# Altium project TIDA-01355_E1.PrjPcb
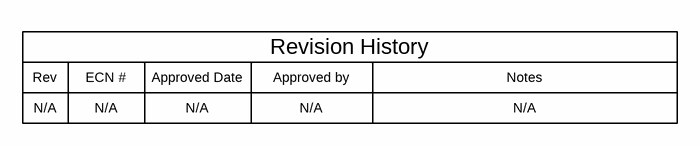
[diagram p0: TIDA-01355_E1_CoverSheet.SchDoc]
CopyrightYear: 2016; PCB_Layout: Sharad Yadav; PCB_Rev: E1; PRJ_Customer: Public Release; PRJ_Engineer: Sharad Yadav; PRJ_Number: XX####; PRJ_Title: 73dB SNR, 7.5MSPS, 14-bit Analog Front-end Using Time-Interleaved SAR ADCs; SCH_Rev: E1; TechSupport: http://www.ti.com/support; TID: TIDA-01355
3 sheets, 92 parts. Net scope: global (net labels, ports and power ports of the same name join across sheets).
Board file: TIDA-01355_E1_PCB.PcbDoc
Sheets:
  TIDA-01355_E1_CoverSheet.SchDoc
  TIDA-01355_E1_EVM_Hardware.SchDoc
  TIDA-01355_E1_AFE_Circuit.SchDoc

## Sheet TIDA-01355_E1_CoverSheet.SchDoc: Block Diagram
size 431 x 279 mm; Date: Not shown in title block; ApprovedBy: Not shown in title block; CheckedBy: Not shown in title block; Author: Not shown in title block; CompanyName: Not shown in title block; DrawnBy: Sharad Yadav; Engineer: Sharad Yadav; Organization: Not shown in title block; Address1: Not shown in title block; Address2: Not shown in title block; Address3: Not shown in title block; Address4: Not shown in title block; DocumentNumber: 1; Revision: Use project parameter SCH_Rev; SheetNumber: 1; SheetTotal: 3; PageSetup: Record=PageOptions¦CenterHorizontal=True¦CenterVertical=True¦PrintScale=1.00¦XCorrection=1.00¦YCorrection=1.00¦PrintKind=0¦BorderSize=5000000¦LeftOffset=0¦BottomOffset=0¦Orientation=2¦PaperLength=1000¦PaperWidth=1000¦Scale=100¦PaperSource=15¦PrintQuality=600¦MediaType=1¦DitherType=10¦PaperKind=Letter¦PrintScaleMode=1

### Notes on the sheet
- Rev
- N/A
- ECN #
- Approved Date
- Approved by
- Revision History
- Notes

## Sheet TIDA-01355_E1_EVM_Hardware.SchDoc: Hardware
size 431 x 279 mm; Date: Not shown in title block; ApprovedBy: Not shown in title block; CheckedBy: Not shown in title block; Author: Not shown in title block; CompanyName: Not shown in title block; DrawnBy: Sharad Yadav; Engineer: Sharad Yadav; Organization: Not shown in title block; Address1: Not shown in title block; Address2: Not shown in title block; Address3: Not shown in title block; Address4: Not shown in title block; DocumentNumber: 1; Revision: Use project parameter SCH_Rev; SheetNumber: 3; SheetTotal: 3; PageSetup: Record=PageOptions¦CenterHorizontal=True¦CenterVertical=True¦PrintScale=1.00¦XCorrection=1.00¦YCorrection=1.00¦PrintKind=0¦BorderSize=5000000¦LeftOffset=0¦BottomOffset=0¦Orientation=2¦PaperLength=1000¦PaperWidth=1000¦Scale=100¦PaperSource=15¦PrintQuality=600¦MediaType=1¦DitherType=10¦PaperKind=Letter¦PrintScaleMode=1
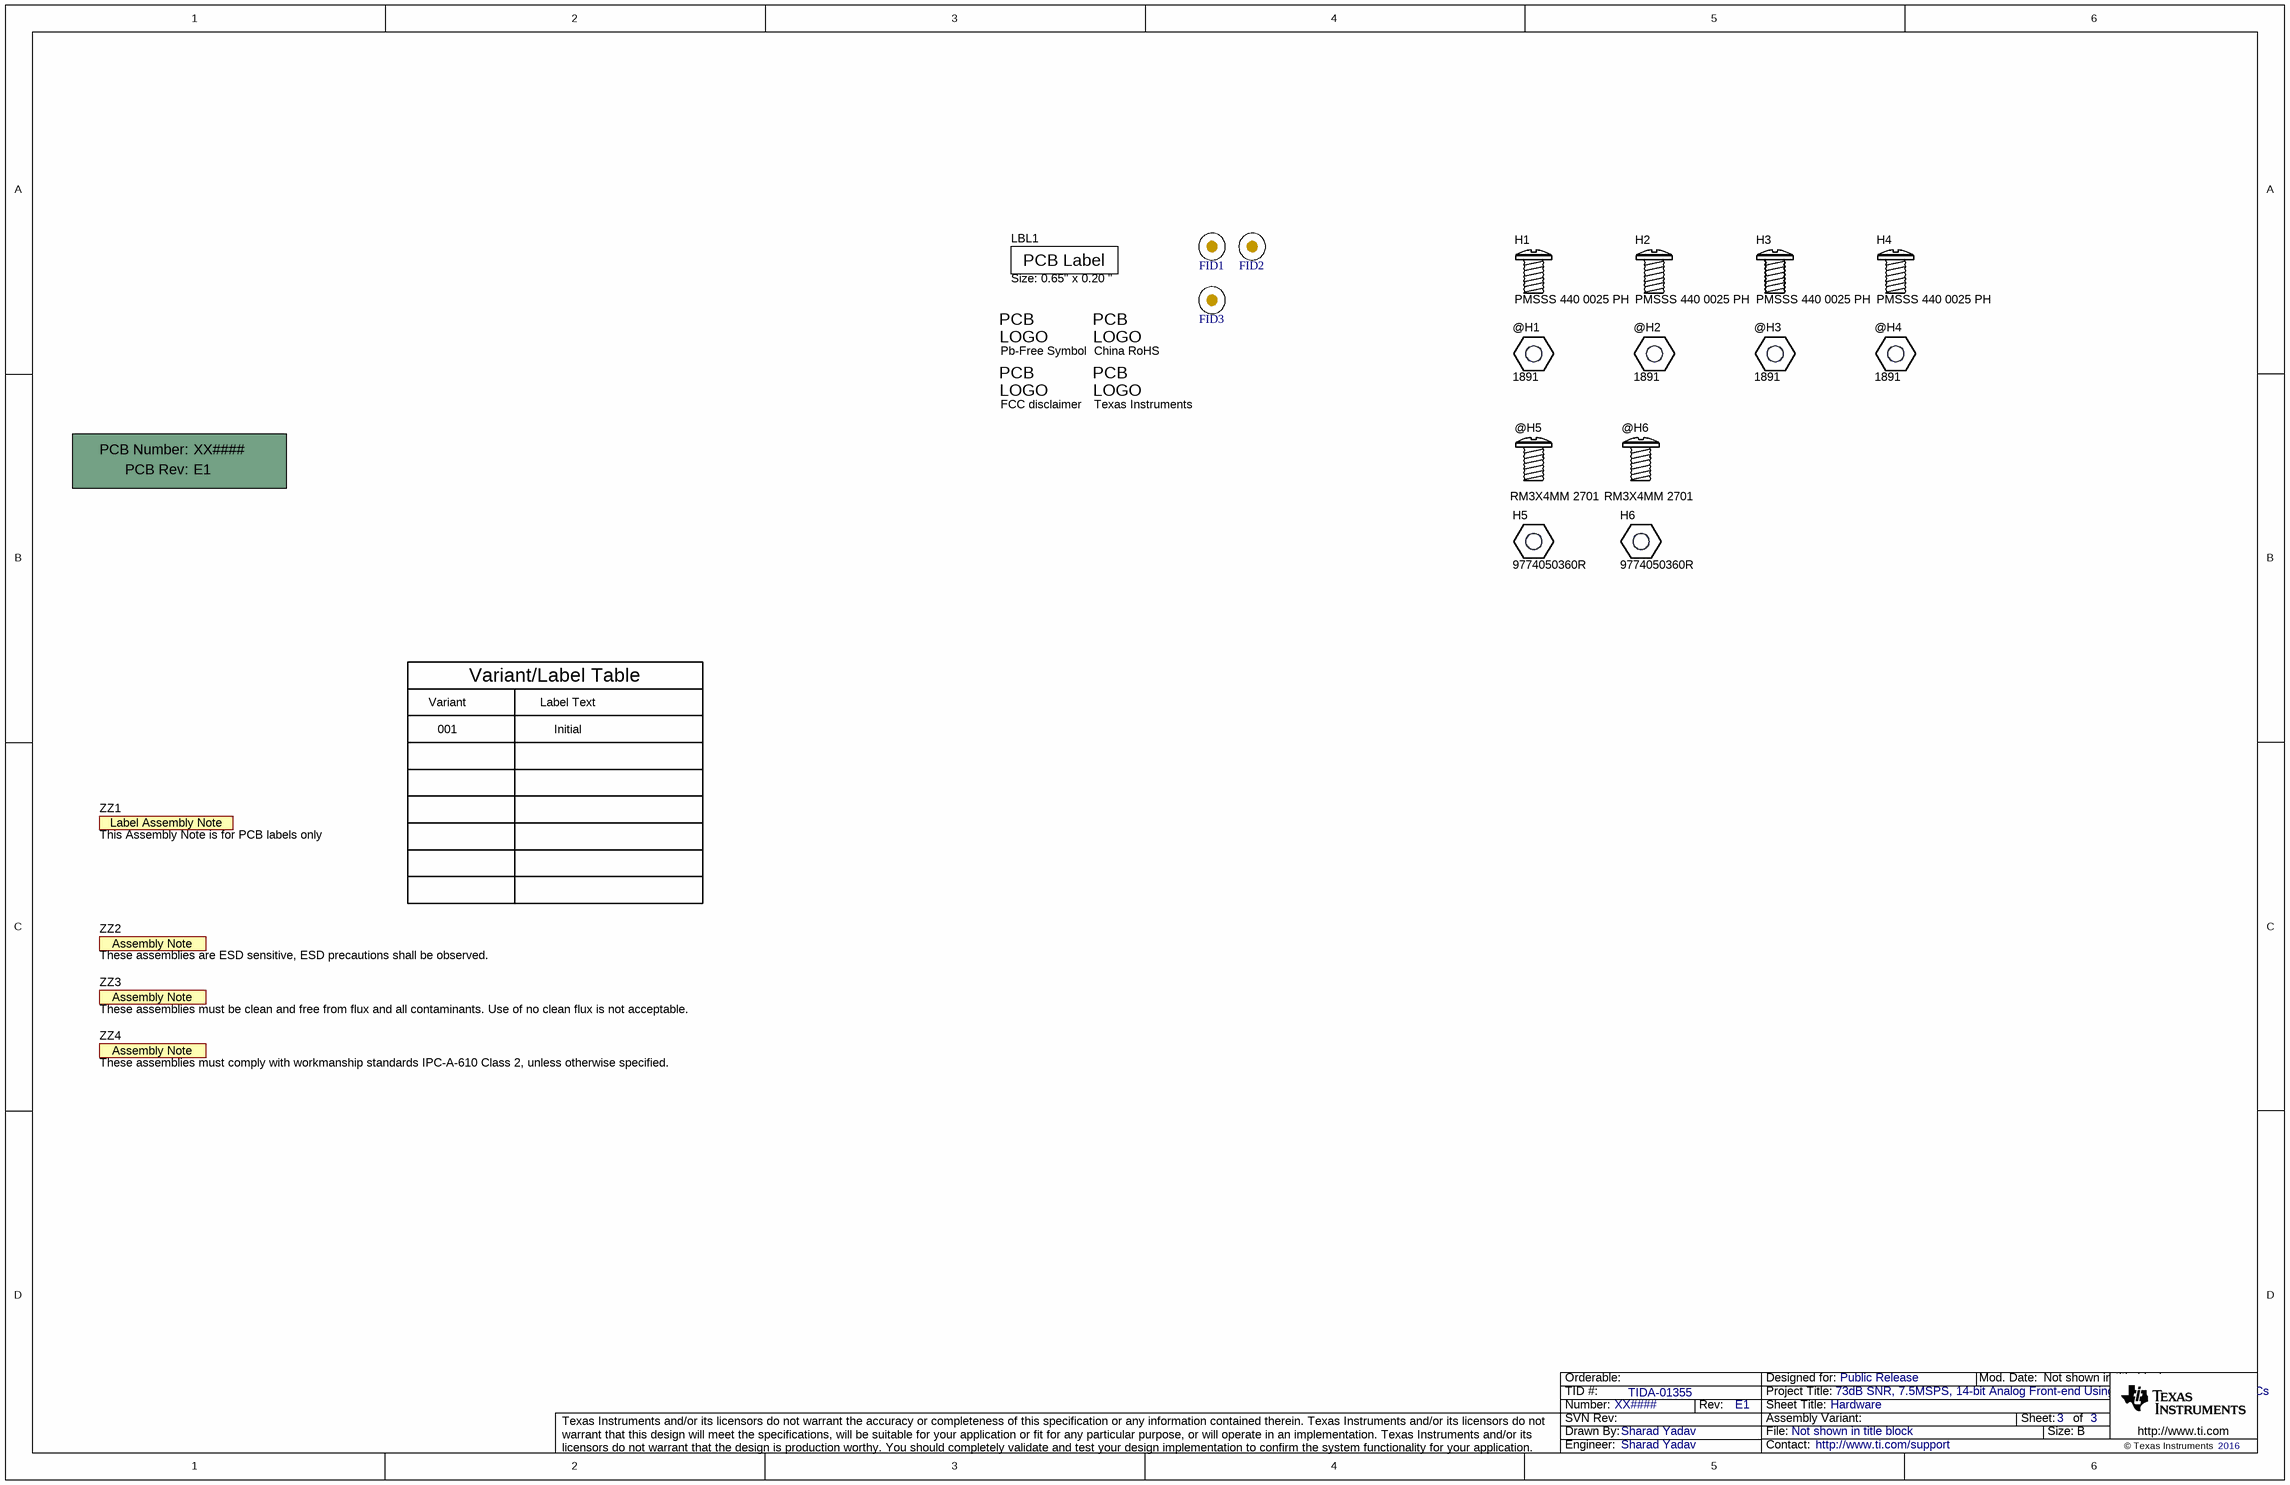
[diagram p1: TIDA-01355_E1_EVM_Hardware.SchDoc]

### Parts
!PCB  Printed Circuit Board  (value not drawn)  (mechanical)
@H1  1891  [Keystone_1891]  (mechanical)
@H2  1891  [Keystone_1891]  (mechanical)
@H3  1891  [Keystone_1891]  (mechanical)
@H4  1891  [Keystone_1891]  (mechanical)
@H5  RM3X4MM 2701  (mechanical)
@H6  RM3X4MM 2701  (mechanical)
FID1  Fiducial  [Fiducial10-30]  (value not drawn)  (no BOM)
FID2  Fiducial  [Fiducial10-30]  (value not drawn)  (no BOM)
FID3  Fiducial  [Fiducial10-30]  (value not drawn)  (no BOM)
H1  PMSSS 440 0025 PH  [B_F_PMSSS4400025PH]
H2  PMSSS 440 0025 PH  [B_F_PMSSS4400025PH]
H3  PMSSS 440 0025 PH  [B_F_PMSSS4400025PH]
H4  PMSSS 440 0025 PH  [B_F_PMSSS4400025PH]
H5  9774050360R  [Wurth_WA-SMSI]
H6  9774050360R  [Wurth_WA-SMSI]
LBL1  Size: 0.65" x 0.20 "  [Label_650x200]
Logo1  Pb-Free Symbol  [Pb-Free_Overlay_Medium]  (no BOM)
Logo2  China RoHS  [ChinaRoHS_5mm]  (no BOM)
Logo3  FCC disclaimer  [FCC_disclaimer_stacked]  (no BOM)
Logo4  Texas Instruments  [TI_Stacked_Overlay_Small]  (no BOM)
ZZ1  This Assembly Note is for PCB labels only  [AssemblyNoteLabel]  (no BOM)
ZZ2  These assemblies are ESD sensitive, ESD precautions shall be observed.  [AssemblyNote]  (no BOM)
ZZ3  These assemblies must be clean and free from flux and all contaminants. Use of no clean flux is not acceptable.  [AssemblyNote]  (no BOM)
ZZ4  These assemblies must comply with workmanship standards IPC-A-610 Class 2, unless otherwise specified.  [AssemblyNote]  (no BOM)

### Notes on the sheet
- Variant
- Variant/Label Table
- Label Text
- 001
- Initial

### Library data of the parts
!PCB = PCB: Manufacturer: Any; PartNumber: XX####; SymbolCreator: a0412235
@H1-@H4 = 1891: 3/16 Hex Female Standoff; Manufacturer: Keystone; SymbolCreator: a0412235
@H5 @H6 = RM3X4MM 2701: Machine Screw Pan PHILLIPS M3; Manufacturer: APM HEXSEAL; SymbolCreator: a0412235; CompType: Standoff
FID1-FID3 = Fiducial: Fiducial mark.  There is nothing to buy or mount.; SymbolCreator: codlsc
H1-H4 = PMSSS 440 0025 PH: MACHINE SCREW PAN PHILLIPS 4-40; Manufacturer: B&F Fastener Supply; SymbolCreator: a0412235; CompType: Standoff
H5 H6 = 9774050360R: ROUND STANDOFF M3 STEEL 5MM; Manufacturer: Wurth Elektronik; SymbolCreator: a0412235
LBL1 = THT-14-423-10: Thermal Transfer Printable Labels, 0.650" W x 0.200" H - 10,000 per roll; Manufacturer: Brady; SymbolCreator: a0412235; CompType: Label
Logo1 = Pb-Free: SymbolCreator: a0412235
Logo2 = RoHS_China: China RoHS Symbol; SymbolCreator: a0412235
Logo3 = FCC_disclaimer: SymbolCreator: codlsc
Logo4 = TI_Logo: Texas Instrument Corporate Signature; SymbolCreator: codlsc
ZZ1 = AssemblyNoteLabel: SymbolCreator: a0412235
ZZ2-ZZ4 = AssemblyNote: SymbolCreator: codlsc

## Sheet TIDA-01355_E1_AFE_Circuit.SchDoc: Analog Front-end for SAR ADC
size 431 x 279 mm; Date: Not shown in title block; ApprovedBy: Not shown in title block; CheckedBy: Not shown in title block; Author: Not shown in title block; CompanyName: Not shown in title block; DrawnBy: Sharad Yadav; Engineer: Sharad Yadav; Organization: Not shown in title block; Address1: Not shown in title block; Address2: Not shown in title block; Address3: Not shown in title block; Address4: Not shown in title block; DocumentNumber: 1; Revision: Use project parameter SCH_Rev; SheetNumber: 2; SheetTotal: 3; PageSetup: Record=PageOptions¦CenterHorizontal=True¦CenterVertical=True¦PrintScale=1.00¦XCorrection=1.00¦YCorrection=1.00¦PrintKind=0¦BorderSize=5000000¦LeftOffset=0¦BottomOffset=0¦Orientation=2¦PaperLength=1000¦PaperWidth=1000¦Scale=100¦PaperSource=15¦PrintQuality=600¦MediaType=1¦DitherType=10¦PaperKind=Letter¦PrintScaleMode=1
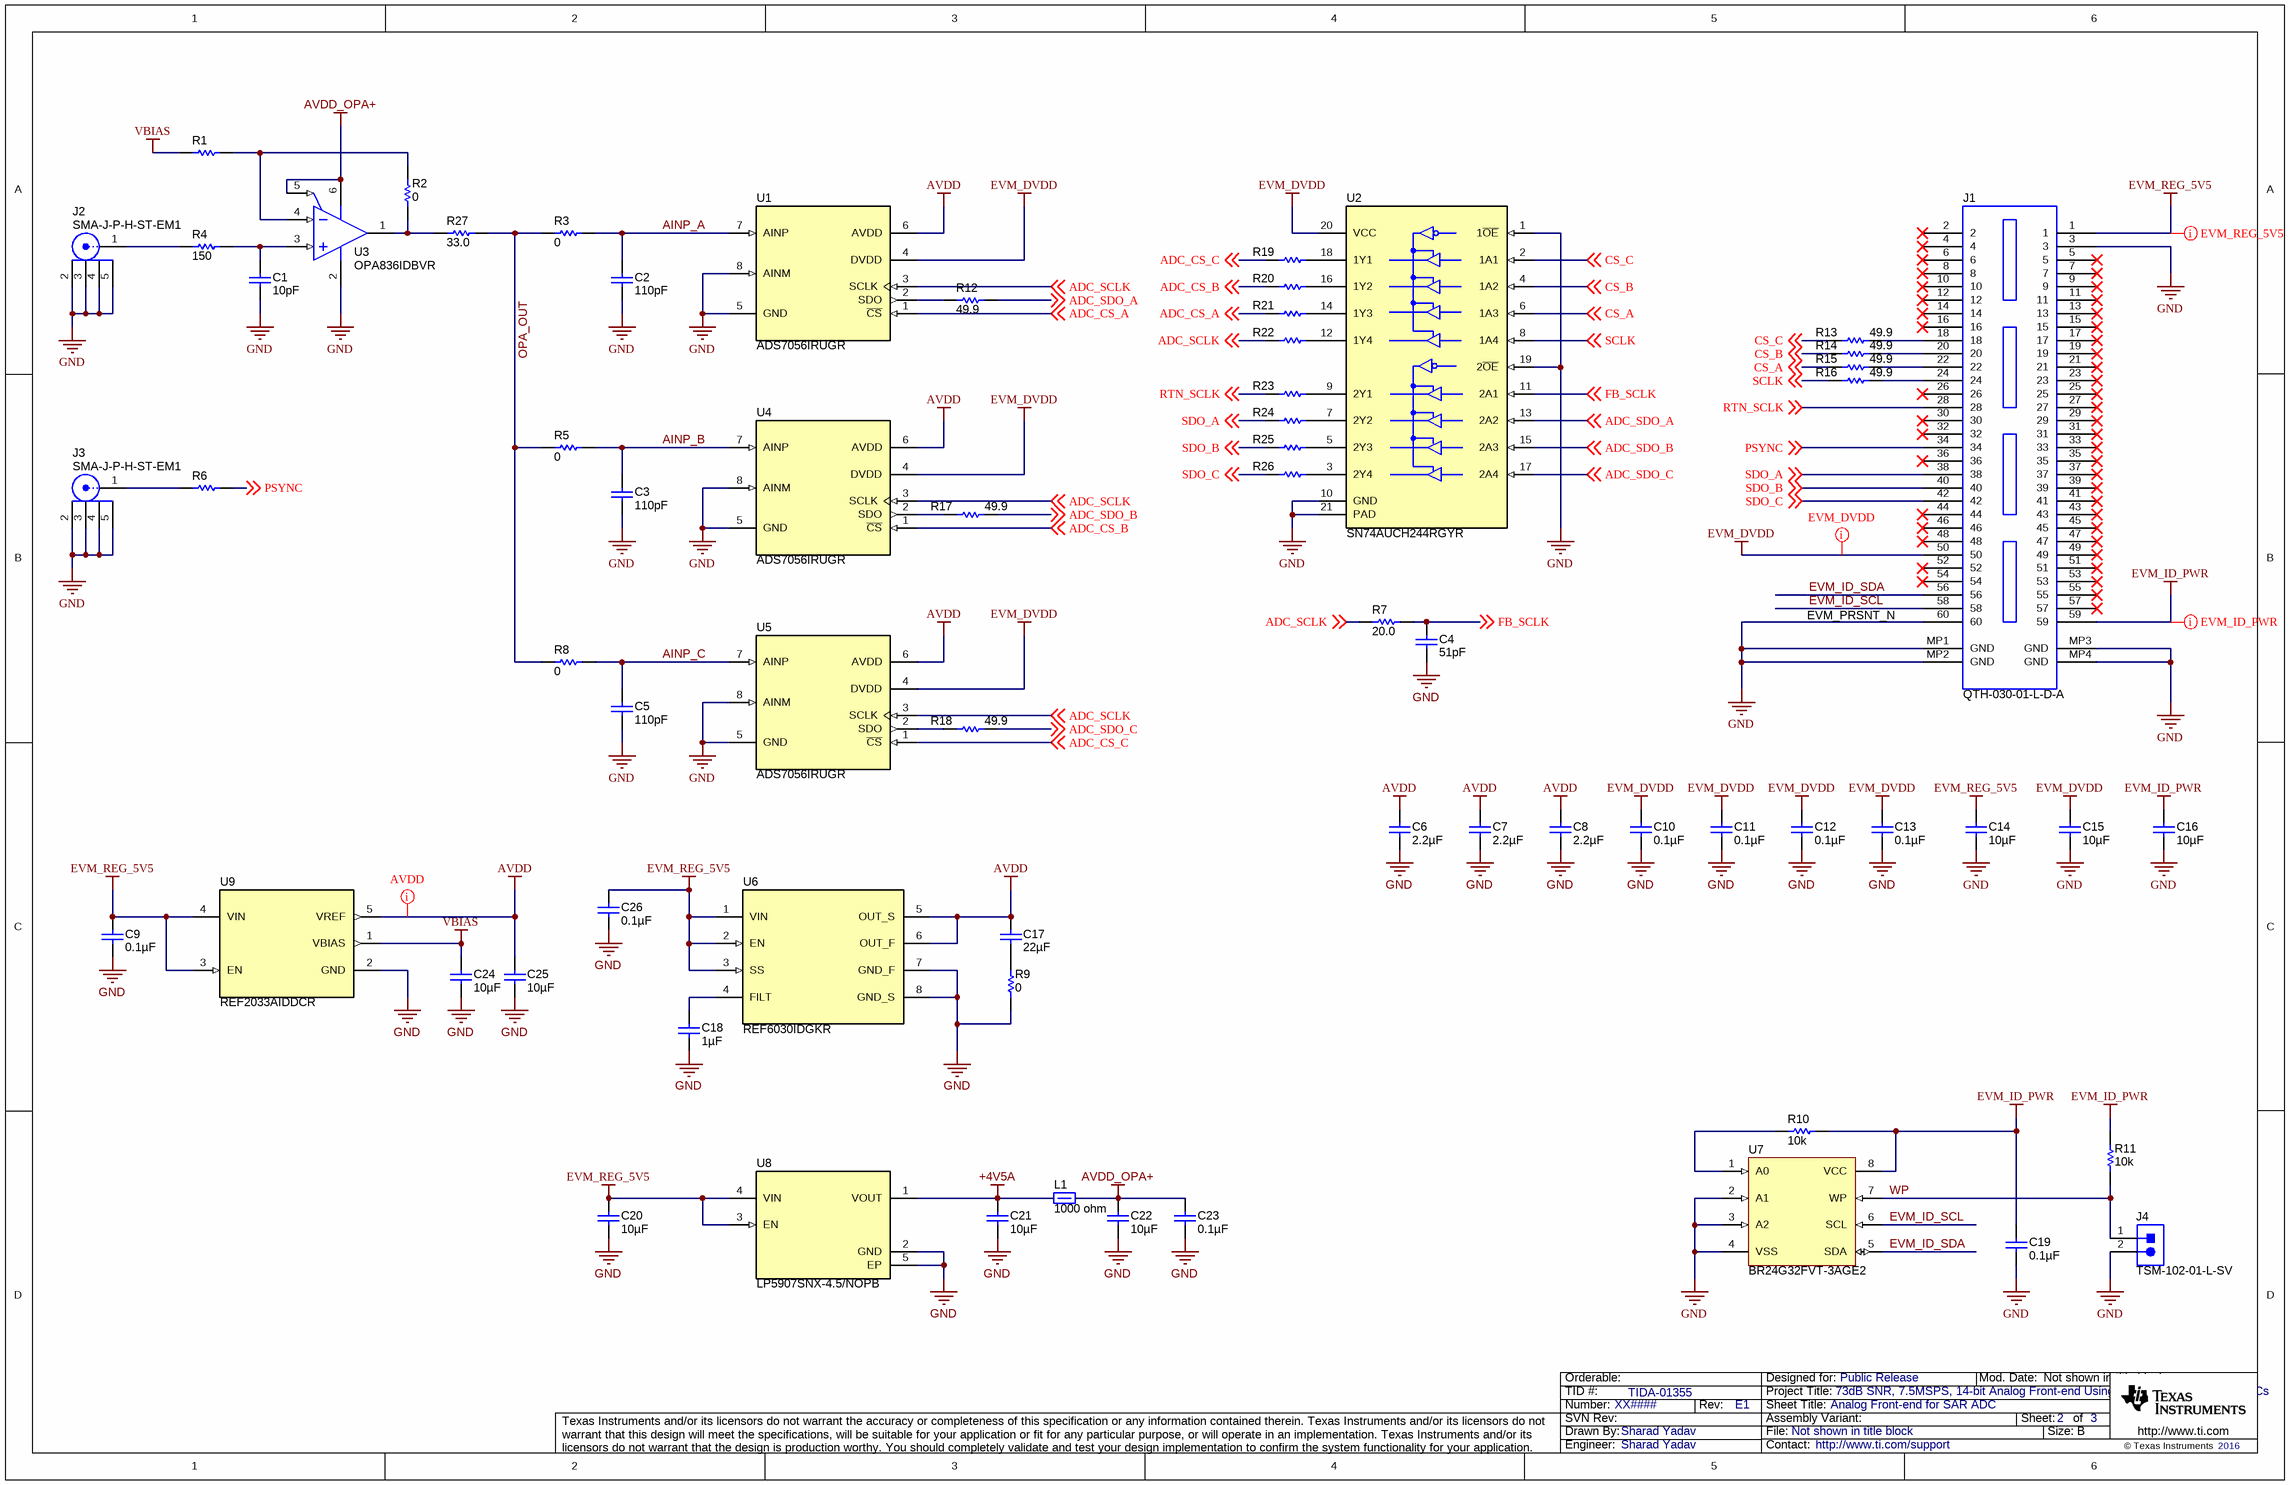
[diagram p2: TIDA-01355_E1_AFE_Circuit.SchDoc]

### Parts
C1  ValueDisplayed: 10pF  [0402S]  (hidden comment: GRM1555C1H100JA01D)
C2  ValueDisplayed: 110pF  [0402S]  (hidden comment: GRM1555C1E111JA01D)
C3  ValueDisplayed: 110pF  [0402S]  (hidden comment: GRM1555C1E111JA01D)
C4  ValueDisplayed: 51pF  [0402S]  (hidden comment: GRM1555C1E510JA01D)
C5  ValueDisplayed: 110pF  [0402S]  (hidden comment: GRM1555C1E111JA01D)
C6  ValueDisplayed: 2.2µF  [0402S]  (hidden comment: C1005X5R1C225K050BC)
C7  ValueDisplayed: 2.2µF  [0402S]  (hidden comment: C1005X5R1C225K050BC)
C8  ValueDisplayed: 2.2µF  [0402S]  (hidden comment: C1005X5R1C225K050BC)
C9  ValueDisplayed: 0.1µF  [0402S]  (hidden comment: 885012205037)
C10  ValueDisplayed: 0.1µF  [0402S]  (hidden comment: 885012205037)
C11  ValueDisplayed: 0.1µF  [0402S]  (hidden comment: 885012205037)
C12  ValueDisplayed: 0.1µF  [0402S]  (hidden comment: 885012205037)
C13  ValueDisplayed: 0.1µF  [0402S]  (hidden comment: 885012205037)
C14  ValueDisplayed: 10µF  [0402S]  (hidden comment: CL05A106MP5NUNC)
C15  ValueDisplayed: 10µF  [0402S]  (hidden comment: CL05A106MP5NUNC)
C16  ValueDisplayed: 10µF  [0402S]  (hidden comment: CL05A106MP5NUNC)
C17  ValueDisplayed: 22µF  [0402_080S]  (hidden comment: LDK105EBJ226MV-F)
C18  ValueDisplayed: 1µF  [0402_070]  (hidden comment: GCM155C71A105KE38D)
C19  ValueDisplayed: 0.1µF  [0402S]  (hidden comment: 885012205037)
C20  ValueDisplayed: 10µF  [0402S]  (hidden comment: CL05A106MP5NUNC)
C21  ValueDisplayed: 10µF  [0402S]  (hidden comment: CL05A106MP5NUNC)
C22  ValueDisplayed: 10µF  [0402S]  (hidden comment: CL05A106MP5NUNC)
C23  ValueDisplayed: 0.1µF  [0402S]  (hidden comment: 885012205037)
C24  ValueDisplayed: 10µF  [0402S]  (hidden comment: CL05A106MP5NUNC)
C25  ValueDisplayed: 10µF  [0402S]  (hidden comment: CL05A106MP5NUNC)
C26  ValueDisplayed: 0.1µF  [0402S]  (hidden comment: 885012205037)
J1  QTH-030-01-L-D-A  [Samtec_QTH-030-01-x-D-A]
J2  SMA-J-P-H-ST-EM1  [Samtec_SMA-J-P-H-ST-EM1]
J3  SMA-J-P-H-ST-EM1  [Samtec_SMA-J-P-H-ST-EM1]
J4  TSM-102-01-L-SV  [Samtec_TSM-102-01-L-SV]
L1  value 1000 ohm  [0402S]  (hidden comment: BLM15AX102SN1D)
R1  PCF0402-12-3K32BT1  [0402S]  (value not drawn)
R2  ValueDisplayed: 0  [0402S]  (hidden comment: CRCW04020000Z0ED)
R3  ValueDisplayed: 0  [0402S]  (hidden comment: CRCW04020000Z0ED)
R4  ValueDisplayed: 150  [0402S]  (hidden comment: CRCW0402150RJNED)
R5  ValueDisplayed: 0  [0402S]  (hidden comment: CRCW04020000Z0ED)
R6  CRCW040210R0FKED  [0402S]  (value not drawn)
R7  ValueDisplayed: 20.0  [0402S]  (hidden comment: CRCW040220R0FKED)
R8  ValueDisplayed: 0  [0402S]  (hidden comment: CRCW04020000Z0ED)
R9  ValueDisplayed: 0  [0402S]  (hidden comment: CRCW04020000Z0ED)
R10  ValueDisplayed: 10k  [0402S]  (hidden comment: ERJ-2GEJ103X)
R11  ValueDisplayed: 10k  [0402S]  (hidden comment: ERJ-2GEJ103X)
R12  ValueDisplayed: 49.9  [0201]  (hidden comment: ERJ-1GEF49R9C)
R13  ValueDisplayed: 49.9  [0201]  (hidden comment: ERJ-1GEF49R9C)
R14  ValueDisplayed: 49.9  [0201]  (hidden comment: ERJ-1GEF49R9C)
R15  ValueDisplayed: 49.9  [0201]  (hidden comment: ERJ-1GEF49R9C)
R16  ValueDisplayed: 49.9  [0201]  (hidden comment: ERJ-1GEF49R9C)
R17  ValueDisplayed: 49.9  [0201]  (hidden comment: ERJ-1GEF49R9C)
R18  ValueDisplayed: 49.9  [0201]  (hidden comment: ERJ-1GEF49R9C)
R19  ERJ-1GEF49R9C  [0201]  (value not drawn)
R20  ERJ-1GEF49R9C  [0201]  (value not drawn)
R21  ERJ-1GEF49R9C  [0201]  (value not drawn)
R22  ERJ-1GEF49R9C  [0201]  (value not drawn)
R23  ERJ-1GEF49R9C  [0201]  (value not drawn)
R24  ERJ-1GEF49R9C  [0201]  (value not drawn)
R25  ERJ-1GEF49R9C  [0201]  (value not drawn)
R26  ERJ-1GEF49R9C  [0201]  (value not drawn)
R27  ValueDisplayed: 33.0  [0402S]  (hidden comment: ERJ-2RKF33R0X)
U1  ADS7056IRUGR  [RUG0008A]
U2  SN74AUCH244RGYR  [RGY0020A]
U3  OPA836IDBVR  [DBV0006A_N]
U4  ADS7056IRUGR  [RUG0008A]
U5  ADS7056IRUGR  [RUG0008A]
U6  REF6030IDGKR  [DGK0008A_N]
U7  BR24G32FVT-3AGE2  [TSOP65P640X120-8N]
U8  LP5907SNX-4.5/NOPB  [DQN0004A]
U9  REF2033AIDDCR  [DDC0005A_N]

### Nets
+4V5A: C21.1 L1.1 U8.1(VOUT)
AVDD: C6.1 C7.1 C8.1 C17.1 C25.1 U1.6(AVDD) U4.6(AVDD) U5.6(AVDD) U6.5(OUT_S) U6.6(OUT_F) U9.5(VREF)
AVDD_OPA+: C22.1 C23.1 L1.2 U3.5(~{PD}) U3.6(VS+)
EVM_DVDD: C10.1 C11.1 C12.1 C13.1 C15.1 J1.50 U1.4(DVDD) U2.20(VCC) U4.4(DVDD) U5.4(DVDD)
EVM_ID_PWR: C16.1 C19.1 J1.59 R10.2 R11.2 U7.8(VCC)
EVM_REG_5V5: C9.1 C14.1 C20.1 C26.1 J1.1 U6.1(VIN) U6.2(EN) U6.3(SS) U8.3(EN) U8.4(VIN) U9.3(EN) U9.4(VIN)
GND: C1.2 C2.2 C3.2 C4.2 C5.2 C6.2 C7.2 C8.2 C9.2 C10.2 C11.2 C12.2 C13.2 C14.2 C15.2 C16.2 C18.2 C19.2 C20.2 C21.2 C22.2 C23.2 C24.2 C25.2 C26.2 J1.3 J1.60 J1.MP1(GND) J1.MP2(GND) J1.MP3(GND) J1.MP4(GND) J2.2 J2.3 J2.4 J2.5 J3.2 J3.3 J3.4 J3.5 J4.2 R9.1 U1.5(GND) U1.8(AINM) U2.1(1~{OE}) U2.10(GND) U2.19(2~{OE}) U2.21(PAD) U3.2(VS-) U4.5(GND) U4.8(AINM) U5.5(GND) U5.8(AINM) U6.7(GND_F) U6.8(GND_S) U7.2(A1) U7.3(A2) U7.4(VSS) U8.2(GND) U8.5(EP) U9.2(GND)
VBIAS: C24.1 R1.1 U9.1(VBIAS)
ADC_CS_A: R21.1 U1.1(~{CS}) ; off-sheet ADC_CS_A
ADC_CS_B: R20.1 U4.1(~{CS}) ; off-sheet ADC_CS_B
ADC_CS_C: R19.1 U5.1(~{CS}) ; off-sheet ADC_CS_C
ADC_SCLK: R7.1 R22.1 U1.3(SCLK) U4.3(SCLK) U5.3(SCLK) ; off-sheet ADC_SCLK
ADC_SDO_A: R12.2 U2.13(2A2) ; off-sheet ADC_SDO_A
ADC_SDO_B: R17.2 U2.15(2A3) ; off-sheet ADC_SDO_B
ADC_SDO_C: R18.2 U2.17(2A4) ; off-sheet ADC_SDO_C
AINP_A: C2.1 R3.1 U1.7(AINP)
AINP_B: C3.1 R5.1 U4.7(AINP)
AINP_C: C5.1 R8.1 U5.7(AINP)
CS_A: R15.1 U2.6(1A3) ; off-sheet CS_A
CS_B: R14.1 U2.4(1A2) ; off-sheet CS_B
CS_C: R13.1 U2.2(1A1) ; off-sheet CS_C
EVM_ID_SCL: J1.58 U7.6(SCL)
EVM_ID_SDA: J1.56 U7.5(SDA)
FB_SCLK: C4.1 R7.2 U2.11(2A1) ; off-sheet FB_SCLK
OPA_OUT: R3.2 R5.2 R8.2 R27.2
PSYNC: J1.34 R6.2 ; off-sheet PSYNC
RTN_SCLK: J1.28 R23.1 ; off-sheet RTN_SCLK
SCLK: R16.1 U2.8(1A4) ; off-sheet SCLK
SDO_A: J1.38 R24.1 ; off-sheet SDO_A
SDO_B: J1.40 R25.1 ; off-sheet SDO_B
SDO_C: J1.42 R26.1 ; off-sheet SDO_C
WP: J4.1 R11.1 U7.7(WP)
NetC1_1: C1.1 R4.2 U3.3(VIN+)
NetC17_2: C17.2 R9.2
NetC18_1: C18.1 U6.4(FILT)
NetJ1_18: J1.18 R13.2
NetJ1_20: J1.20 R14.2
NetJ1_22: J1.22 R15.2
NetJ1_24: J1.24 R16.2
NetJ2_1: J2.1 R4.1
NetJ3_1: J3.1 R6.1
NetR1_2: R1.2 R2.1 U3.4(VIN-)
NetR2_2: R2.2 R27.1 U3.1(VOUT)
NetR10_1: R10.1 U7.1(A0)
NetR12_1: R12.1 U1.2(SDO)
NetR17_1: R17.1 U4.2(SDO)
NetR18_1: R18.1 U5.2(SDO)
NetR19_2: R19.2 U2.18(1Y1)
NetR20_2: R20.2 U2.16(1Y2)
NetR21_2: R21.2 U2.14(1Y3)
NetR22_2: R22.2 U2.12(1Y4)
NetR23_2: R23.2 U2.9(2Y1)
NetR24_2: R24.2 U2.7(2Y2)
NetR25_2: R25.2 U2.5(2Y3)
NetR26_2: R26.2 U2.3(2Y4)

Not connected (* = marked no-connect by the designer): J1 2* 4* 5* 6* 7* 8* 9* 10* 11* 12* 13* 14* 15* 16* 17* 19* 21* 23* 25* 26* 27* 29* 30* 31* 32* 33* 35* 36* 37* 39* 41* 43* 44* 45* 46* 47* 48* 49* 51* 52* 53* 54* 55* 57*

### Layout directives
net class AVDD: AVDD
net class EVM_REG_5V5: EVM_REG_5V5
net class EVM_DVDD: EVM_DVDD
net class EVM_ID_PWR: EVM_ID_PWR

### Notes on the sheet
- EVM_PRSNT_N

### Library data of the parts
C1 = GRM1555C1H100JA01D: CAP, CERM, 10 pF, 50 V, +/- 5%, C0G/NP0, 0402; Manufacturer: MuRata; Polarized: N; CompType: Capacitor; Value: 10pF; U/M: EA; Cap_F: 0.00000000001; Tolerance_%: 5; Value1: Unknown; VDC_V: 50; Value2: 50V; TaMin_C: -55; TaMax_C: 125; Cap_Case: 0402; SizeArea_mm2: 0.5; SizeAreaWB_mm2: 3; SizeX_mm: 1; SizeZ_mm: 0.6; AEC Category: Q200
C2 C3 C5 = GRM1555C1E111JA01D: CAP, CERM, 110 pF, 25 V, +/- 5%, C0G/NP0, 0402; Manufacturer: MuRata; Polarized: N; CompType: Capacitor; Value: 110pF; U/M: EA; Cap_F: 0.00000000011; Tolerance_%: 5; Value1: Unknown; VDC_V: 25; Value2: 25V; TaMin_C: -55; TaMax_C: 125; Cap_Case: 0402; SizeArea_mm2: 0.5; SizeAreaWB_mm2: 3; SizeX_mm: 1; SizeZ_mm: 0.6; AEC Category: Q200
C4 = GRM1555C1E510JA01D: CAP, CERM, 51 pF, 25 V, +/- 5%, C0G/NP0, 0402; Manufacturer: MuRata; Polarized: N; CompType: Capacitor; Value: 51pF; U/M: EA; Cap_F: 0.000000000051; Tolerance_%: 5; Value1: Unknown; VDC_V: 25; Value2: 25V; TaMin_C: -55; TaMax_C: 125; Cap_Case: 0402; SizeArea_mm2: 0.5; SizeAreaWB_mm2: 3; SizeX_mm: 1; SizeZ_mm: 0.6; AEC Category: Q200
C6-C8 = C1005X5R1C225K050BC: CAP, CERM, 2.2 µF, 16 V, +/- 10%, X5R, 0402; Manufacturer: TDK; Polarized: N; CompType: Capacitor; Value: 2.2uF; U/M: EA; Cap_F: 0.0000022; Tolerance_%: 10; Value1: Unknown; VDC_V: 16; Value2: 16V; TaMin_C: -55; TaMax_C: 85; Cap_Case: 0402; SizeArea_mm2: 0.5; SizeAreaWB_mm2: 3; SizeX_mm: 1; SizeZ_mm: 0.6; AEC Category: Q200
C9-C13 C19 C23 C26 = 885012205037: CAP, CERM, 0.1 µF, 16 V, +/- 10%, X7R, 0402; Manufacturer: Wurth Elektronik; Polarized: N; CompType: Capacitor; Value: 0.1uF; U/M: EA; Cap_F: 0.0000001; Tolerance_%: 10; Value1: Unknown; VDC_V: 16; Value2: 16V; TaMin_C: -55; TaMax_C: 125; Cap_Case: 0402; SizeArea_mm2: 0.5; SizeAreaWB_mm2: 3; SizeX_mm: 1; SizeZ_mm: 0.6; AEC Category: Q200
C14-C16 C20-C22 C24 C25 = CL05A106MP5NUNC: CAP, CERM, 10 µF, 10 V, +/- 20%, X5R, 0402; Manufacturer: Samsung Electro-Mechanics; Polarized: N; CompType: Capacitor; Value: 10uF; U/M: EA; Cap_F: 0.00001; Tolerance_%: 20; Value1: Unknown; VDC_V: 10; Value2: 10V; TaMin_C: -55; TaMax_C: 85; Cap_Case: 0402; SizeArea_mm2: 0.5; SizeAreaWB_mm2: 3; SizeX_mm: 1; SizeZ_mm: 0.6; AEC Category: Q200; Green_Lifecycle: Active; Green_REACh: Passed
C17 = LDK105EBJ226MV-F: CAP, CERM, 22 µF, 10 V, +/- 20%, X5R, 0402; Manufacturer: Taiyo Yuden; Polarized: N; CompType: Capacitor; Value: 22uF; U/M: EA; Cap_F: 0.000022; Tolerance_%: 20; Value1: Unknown; VDC_V: 10; Value2: 10V; TaMin_C: -55; TaMax_C: 105; Cap_Case: 0402; SizeArea_mm2: 0.5; SizeAreaWB_mm2: 3; SizeX_mm: 1; SizeZ_mm: 0.8; AEC Category: Q200
C18 = GCM155C71A105KE38D: CAP, CERM, 1 µF, 10 V, +/- 10%, X7S, AEC-Q200 Grade 1, 0402; Manufacturer: MuRata; Polarized: N; CompType: Capacitor; Value: 1uF; U/M: EA; Cap_F: 0.000001; Tolerance_%: 10; Value1: Unknown; Value2: 10V; TaMin_C: -55; TaMax_C: 125; Cap_Case: 0402; SizeArea_mm2: 0.5; SizeAreaWB_mm2: 3; SizeX_mm: 1; SizeZ_mm: 0.7; AEC Category: Q200; AEC Qualified: Y
J1 = QTH-030-01-L-D-A: Header(Shrouded), 19.7mil, 30x2, Gold, SMT; Manufacturer: Samtec; SymbolCreator: Altium; Pitch_mm: 0.5; Gender: Male; Shrouded: Y; Row_Count: 2
J2 J3 = SMA-J-P-H-ST-EM1: SMA Jack, 50 Ohm, Gold, R/A, SMT; Manufacturer: Samtec; SymbolCreator: X0208326; Pitch_mm: 2.825; Gender: Female; Shrouded: Y; Voltage_V: 335
J4 = TSM-102-01-L-SV: Header, 100mil, 2x1, Gold with Tin Tail, SMT; Manufacturer: Samtec; SymbolCreator: a0412235; Pitch_mm: 2.54; Gender: Male; Shrouded: N; Row_Count: 1; Current_A: 5.4; Voltage_V: 475; Cert_CSA: Y
L1 = BLM15AX102SN1D: Ferrite Bead, 1000 ohm @ 100 MHz, 0.35 A, 0402; Manufacturer: MuRata; Imax_A: 0.35; DCR_ohm: 0.49; Value1: 0.49 ohm; Value2: 0.35A; ZTyp@100MHz_Ohm: 1000
R1 = PCF0402-12-3K32BT1: RES, 3.32 k, 0.1%, 0.063 W, 0402; Manufacturer: TT Electronics/IRC; CompType: Resistor; Value: 3.32k; Res_ohm: 3320; Value_Code: 3k32; Tolerance_%: 0.1; Power_W: 0.063; Value2: 0.063W; VDC_V: 25; TempCo: 10 ppm/C; SizeArea_mm2: 0.5; SizeX_mm: 1; SizeZ_mm: 0.6; EIA_Code: E192; U/M: EA; AEC Category: Q200; AEC Qualified: N
R2 R3 R5 R8 R9 = CRCW04020000Z0ED: RES, 0, 5%, 0.063 W, 0402; Manufacturer: Vishay-Dale; CompType: Resistor; Value: 0; Value_Code: 0000; Tolerance_%: 5; Power_W: 0.063; Value2: 0.063W; VDC_V: 50; TempCo: 200 ppm/C; SizeArea_mm2: 0.5; SizeX_mm: 1; SizeZ_mm: 0.6; EIA_Code: E24; U/M: EA; AEC Category: Q200
R4 = CRCW0402150RJNED: RES, 150, 5%, 0.063 W, 0402; Manufacturer: Vishay-Dale; CompType: Resistor; Value: 150; Value_Code: 150R; Tolerance_%: 5; Power_W: 0.063; Value2: 0.063W; VDC_V: 50; TempCo: 200 ppm/C; SizeArea_mm2: 0.5; SizeX_mm: 1; SizeZ_mm: 0.6; EIA_Code: E24; U/M: EA; AEC Category: Q200
R6 = CRCW040210R0FKED: RES, 10.0, 1%, 0.063 W, 0402; Manufacturer: Vishay-Dale; CompType: Resistor; Value: 10.0; Res_ohm: 10; Value_Code: 10R0; Tolerance_%: 1; Power_W: 0.063; Value2: 0.063W; VDC_V: 50; TempCo: 100 ppm/C; SizeArea_mm2: 0.5; SizeZ_mm: 0.6; EIA_Code: E96; U/M: EA; AEC Category: Q200
R7 = CRCW040220R0FKED: RES, 20.0, 1%, 0.063 W, 0402; Manufacturer: Vishay-Dale; CompType: Resistor; Value: 20.0; Res_ohm: 20; Value_Code: 20R0; Tolerance_%: 1; Power_W: 0.063; Value2: 0.063W; VDC_V: 50; TempCo: 100 ppm/C; SizeArea_mm2: 0.5; SizeZ_mm: 0.6; EIA_Code: E96; U/M: EA; AEC Category: Q200
R10 R11 = ERJ-2GEJ103X: RES, 10 k, 5%, 0.1 W, AEC-Q200 Grade 0, 0402; Manufacturer: Panasonic; CompType: Resistor; Value: 10k; Res_ohm: 10000; Value_Code: 10k0; Tolerance_%: 5; Power_W: 0.1; Value2: 0.1W; VDC_V: 50; TempCo: 200 ppm/C; SizeArea_mm2: 0.5; SizeX_mm: 1; SizeZ_mm: 0.6; EIA_Code: E24; U/M: EA; AEC Category: Q200; AEC Qualified: Y; AEC Grade: 0
R12-R26 = ERJ-1GEF49R9C: RES, 49.9, 1%, 0.05 W, 0201; Manufacturer: Panasonic; CompType: Resistor; Value: 49.9; Value_Code: 49R9; Tolerance_%: 1; Power_W: 0.05; Value2: 0.05W; VDC_V: 25; TempCo: 200 ppm/C; SizeArea_mm2: 0.18; SizeAreaWB_mm2: 2.08; SizeX_mm: 0.6; SizeY_mm: 0.3; SizeZ_mm: 0.26; EIA_Code: E96; U/M: EA; AEC Category: Q200
R27 = ERJ-2RKF33R0X: RES, 33.0, 1%, 0.1 W, 0402; Manufacturer: Panasonic; CompType: Resistor; Value: 33.0; Res_ohm: 33; Value_Code: 33R0; Tolerance_%: 1; Power_W: 0.1; Value2: 0.1W; VDC_V: 50; TempCo: 100 ppm/C; SizeArea_mm2: 0.5; SizeZ_mm: 0.6; U/M: EA; AEC Category: Q200
U1 U4 U5 = ADS7056IRUGR: Ultra-Low Power, Ultra-Small Size, 14-Bit, 2.5-MSPS, SAR ADC, RUG0008A (X2QFN-8); Manufacturer: Texas Instruments; SymbolCreator: Altium; SizeArea_mm2: 2.25; SizeAreaWB_mm2: 6.25; SizeX_mm: 1.5; SizeZ_mm: 0.4; CompType: IC; U/M: EA
U2 = SN74AUCH244RGYR: Octal Buffer and Driver With 3-State Outputs, RGY0020A; Manufacturer: Texas Instruments; SymbolCreator: Altium; SizeArea_mm2: 15.75; SizeAreaWB_mm2: 24.75; SizeX_mm: 3.5; SizeY_mm: 4.5; SizeZ_mm: 1; CompType: IC; U/M: EA
U3 = OPA836IDBVR: Very Low Power, Rail to Rail Out, Negative Rail In, VFB Operational Amplifier, 2.5 to 5.5 V, -40 to 125 degC, 6-pin SOT23 (DBV6), Green (RoHS & no Sb/Br); Alternate Manufacturer: Texas Instruments; Alternate PartNumber: Equivalent; 2nd Harmonic(dBc): 85; 3rd Harmonic(dBc): 105; @ MHz: 1; BW @ Acl(MHz): 205; Iib(Max)(nA): 1000; Io(Typ)(mA): 50; Settling Time (0.1%)(Typ)(ns): 30; Slew Rate(Typ)(V/us): 560; Sub Family: Audio Operational Amplifier, High Output Current Amplifier (>=50mA), High Speed Amplifier (>=50MHz), Low Noise Amp (<=10nV/rtHz), Low Offset Voltage Amplifier (<=500uV), Low Supply Voltage Amplifier (<=2.7V); Vio(Max)(mV): 0.4; Vn at Flatband(Typ)(nV/rtHz): 4.6; Vs(Max)(V): 5.5; Vs(Min)(V): 2.5
U6 = REF6030IDGKR: High-Precision Voltage Reference with Integrated High-Bandwidth Buffer, DGK0008A; Alternate PartNumber: REF6030IDGKT; Manufacturer: Texas Instruments; SymbolCreator: Altium; SizeArea_mm2: 15.655; SizeAreaWB_mm2: 35.955; SizeX_mm: 5.05; SizeY_mm: 3.1; SizeZ_mm: 1.1; CompType: IC; U/M: EA
U7 = BR24G32FVT-3AGE2: I2C BUS EEPROM (2-Wire), TSSOP-B8; Manufacturer: Rohm; SymbolCreator: a0411947
U8 = LP5907SNX-4.5/NOPB: Ultra Low-Noise, 250-mA Linear Regulator for RF and Analog Circuits, DQN0004A; Manufacturer: Texas Instruments; SymbolCreator: Altium; SizeArea_mm2: 1; SizeAreaWB_mm2: 4; SizeZ_mm: 0.4; CompType: IC; U/M: EA
U9 = REF2033AIDDCR: Low-Drift, Low-Power, Dual-Output, VREF and VREF / 2 Voltage References, DDC0005A; Alternate PartNumber: REF2033AIDDCT; Manufacturer: Texas Instruments; SymbolCreator: a0799628; SizeArea_mm2: 8.12; SizeAreaWB_mm2: 14.82; SizeX_mm: 2.8; SizeY_mm: 2.9; SizeZ_mm: 1.1; CompType: IC; U/M: EA

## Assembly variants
001: not fitted C17 C18 C26 FID1 FID2 FID3 J3 LBL1 R1 R6 R9 U6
